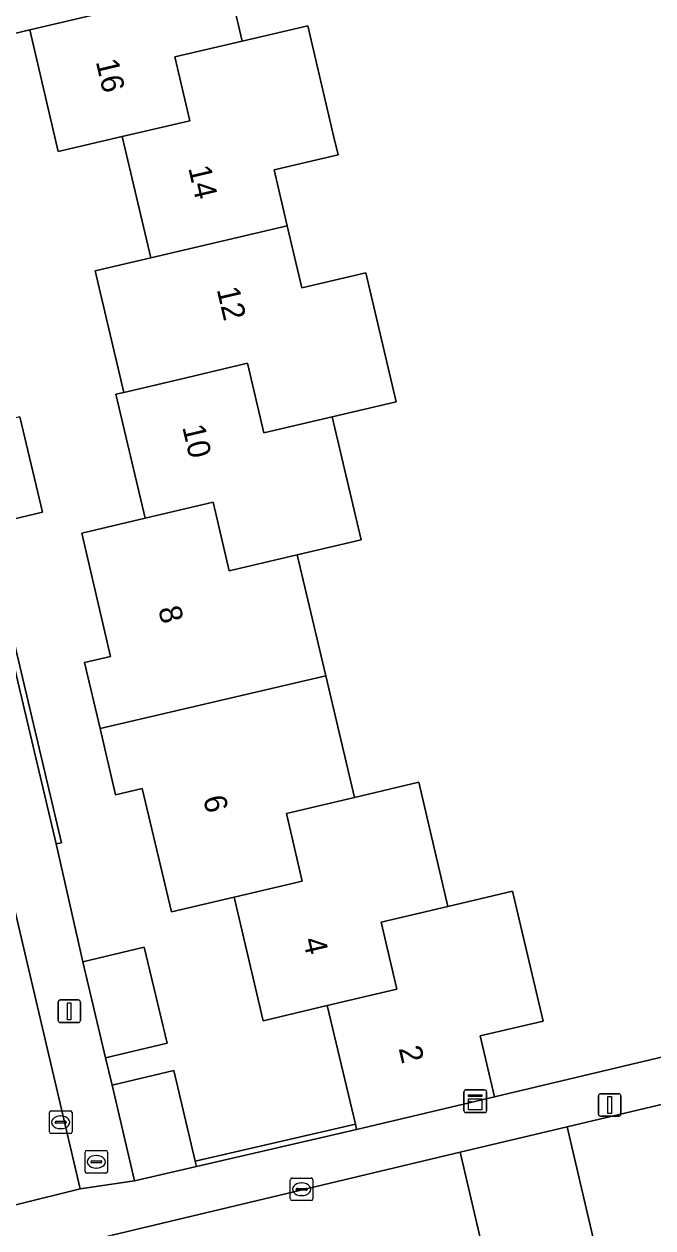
# Model space of a CAD drawing. Extents: x 158031 to 159244, y 380104 to 381214.
# Drawn here: x 158685 to 158712.9, y 380564.3 to 380617.5 of the extents above; entities that cross this region are included whole.
import ezdxf

# ---------------------------------------------------------------- set-up
doc = ezdxf.new("R2010")
doc.units = 0
for name, color, linetype in [('IMGEO_Brandkraan', 7, 'Continuous'), ('IMGEO_Erf', 7, 'Continuous'), ('IMGEO_Hek', 7, 'Continuous'), ('IMGEO_Kast', 7, 'Continuous'), ('IMGEO_Kolk', 7, 'Continuous'), ('IMGEO_Lichtmast', 7, 'Continuous'), ('IMGEO_Muur', 7, 'Continuous'), ('IMGEO_Pand', 7, 'Continuous'), ('IMGEO_Pand_nummerreeks', 7, 'Continuous'), ('IMGEO_Rijbaan_lokaal_open', 7, 'Continuous'), ('IMGEO_Voetpad_open', 7, 'Continuous')]:
    doc.layers.add(name, color=color, linetype=linetype)

msp = doc.modelspace()

# ---------------------------------------------------------------- linework, layer by layer
at = {"layer": 'IMGEO_Brandkraan'}
for p, q in [((158687.739, 380566.802), (158687.739, 380567.654)), ((158687.814, 380567.728), (158688.666, 380567.728)), ((158688.74, 380567.654), (158688.74, 380566.802)), ((158687.998, 380567.222), (158687.998, 380567.234)), ((158688.436, 380567.185), (158688.038, 380567.185)), ((158688.041, 380567.271), (158688.439, 380567.271)), ((158688.227, 380567.508), (158688.252, 380567.508)), ((158688.482, 380567.234), (158688.482, 380567.222)), ((158688.666, 380566.728), (158687.814, 380566.728)), ((158688.25, 380566.948), (158688.225, 380566.948))]:
    msp.add_line(p, q, dxfattribs=at)
for points in [[(158687.739, 380566.802), (158687.739, 380567.654)], [(158687.814, 380567.728), (158688.666, 380567.728)], [(158688.74, 380567.654), (158688.74, 380566.802)], [(158688.666, 380566.728), (158687.814, 380566.728)]]:
    msp.add_lwpolyline(points, dxfattribs=at)
for centre, radius, start, end in [((158687.816, 380567.652), 0.0765, 91.552, 178.448), ((158687.816, 380567.652), 0.0765, 91.552, 178.448), ((158688.664, 380567.652), 0.0765, 1.552, 88.448), ((158688.664, 380567.652), 0.0765, 1.552, 88.448), ((158688.038, 380567.231), 0.0403, 85.8775, 175.7526), ((158688.035, 380567.221), 0.0366, 178.938, 274.7102), ((158688.439, 380567.228), 0.043, 264.8664, 352.4533), ((158688.443, 380567.233), 0.0386, 1.7309, 96.639), ((158687.816, 380566.804), 0.0765, 181.552, 268.448), ((158687.816, 380566.804), 0.0765, 181.552, 268.448), ((158688.664, 380566.804), 0.0765, 271.552, 358.448), ((158688.664, 380566.804), 0.0765, 271.552, 358.448)]:
    msp.add_arc(centre, radius, start, end, dxfattribs=at)
for centre, major_axis, ratio, start_param, end_param in [((158688.226, 380567.228), (-0.387, 0.002), 0.722429, 4.712389, 7.853982), ((158688.251, 380567.228), (-0.39, 0.002), 0.717154, 1.570796, 4.712389)]:
    msp.add_ellipse(centre, major_axis=major_axis, ratio=ratio, start_param=start_param, end_param=end_param, dxfattribs=at)
at = {"layer": 'IMGEO_Erf'}
for points in [[(158693.404, 380622.278), (158694.695, 380616.786), (158697.593, 380617.467), (158698.737, 380612.6), (158698.935, 380611.759), (158696.103, 380611.093), (158696.687, 380608.61), (158697.331, 380605.871), (158700.164, 380606.537), (158701.504, 380600.839), (158698.669, 380600.173), (158699.948, 380594.732), (158697.13, 380594.07), (158698.388, 380588.719), (158699.652, 380583.342), (158702.502, 380584.012), (158703.792, 380578.525), (158706.65, 380579.197), (158708.002, 380573.446), (158705.217, 380572.792), (158705.856, 380570.103), (158725.953, 380574.878)], [(158684.603, 380590.209), (158686.699, 380581.338), (158686.465, 380581.283), (158687.636, 380576.078), (158690.36, 380576.726), (158691.369, 380572.481), (158688.645, 380571.833), (158688.935, 380570.621), (158691.661, 380571.259), (158692.614, 380567.25), (158699.697, 380568.888), (158698.452, 380574.133), (158695.623, 380573.469), (158694.339, 380578.933), (158691.557, 380578.279), (158690.274, 380583.739), (158689.093, 380583.461), (158688.406, 380586.385), (158687.719, 380589.309), (158688.872, 380589.58), (158687.591, 380595.031), (158690.393, 380595.689), (158689.105, 380601.169), (158689.457, 380601.252), (158688.194, 380606.62), (158690.646, 380607.197), (158689.384, 380612.566), (158686.557, 380611.902), (158685.293, 380617.279), (158682.451, 380616.611)], [(158684.859, 380600.175), (158685.852, 380595.949), (158683.126, 380595.308)]]:
    msp.add_lwpolyline(points, dxfattribs=at)
at = {"layer": 'IMGEO_Hek'}
msp.add_lwpolyline([(158705.856, 380570.103), (158725.953, 380574.878)], dxfattribs=at)
at = {"layer": 'IMGEO_Kast'}
for p, q in [((158704.499, 380569.479), (158704.499, 380570.32)), ((158704.499, 380570.32), (158704.499, 380569.479)), ((158704.574, 380570.404), (158705.415, 380570.404)), ((158705.415, 380570.404), (158704.574, 380570.404)), ((158705.499, 380570.329), (158705.499, 380569.488)), ((158705.499, 380569.488), (158705.499, 380570.329)), ((158705.424, 380569.404), (158704.583, 380569.404)), ((158704.583, 380569.404), (158705.424, 380569.404))]:
    msp.add_line(p, q, dxfattribs=at)
for points in [[(158704.694, 380570.194), (158705.294, 380570.194), (158705.294, 380570.109), (158704.694, 380570.109), (158704.694, 380570.194)], [(158704.694, 380570.019), (158705.294, 380570.019), (158705.294, 380569.53), (158704.694, 380569.53), (158704.694, 380570.019)]]:
    msp.add_lwpolyline(points, dxfattribs=at)
msp.add_circle((158704.778, 380569.868), 0.0377, dxfattribs=at)
for centre, start, end in [((158704.577, 380570.326), 92.4484, 184.2845), ((158704.577, 380570.326), 92.4484, 184.2845), ((158705.421, 380570.326), 2.4484, 94.2845), ((158705.421, 380570.326), 2.4484, 94.2845), ((158704.577, 380569.482), 182.4484, 274.2845), ((158704.577, 380569.482), 182.4484, 274.2845), ((158705.421, 380569.482), 272.4484, 4.2845), ((158705.421, 380569.482), 272.4484, 4.2845)]:
    msp.add_arc(centre, 0.0779, start, end, dxfattribs=at)
at = {"layer": 'IMGEO_Kolk'}
for p, q in [((158686.163, 380568.551), (158686.163, 380569.403)), ((158686.238, 380569.477), (158687.09, 380569.477)), ((158686.651, 380569.257), (158686.676, 380569.257)), ((158687.164, 380569.403), (158687.164, 380568.551)), ((158686.422, 380568.971), (158686.422, 380568.983)), ((158686.86, 380568.934), (158686.462, 380568.934)), ((158686.465, 380569.02), (158686.863, 380569.02)), ((158686.906, 380568.983), (158686.906, 380568.971)), ((158687.09, 380568.477), (158686.238, 380568.477)), ((158686.674, 380568.697), (158686.649, 380568.697)), ((158696.82, 380565.586), (158696.82, 380566.438)), ((158696.895, 380566.512), (158697.747, 380566.512)), ((158697.122, 380566.055), (158697.52, 380566.055)), ((158697.308, 380566.292), (158697.333, 380566.292)), ((158697.821, 380566.438), (158697.821, 380565.586)), ((158697.747, 380565.512), (158696.895, 380565.512)), ((158697.079, 380566.006), (158697.079, 380566.018)), ((158697.517, 380565.969), (158697.119, 380565.969)), ((158697.331, 380565.732), (158697.306, 380565.732)), ((158697.563, 380566.018), (158697.563, 380566.006))]:
    msp.add_line(p, q, dxfattribs=at)
for points in [[(158686.163, 380568.551), (158686.163, 380569.403)], [(158686.238, 380569.477), (158687.09, 380569.477)], [(158687.164, 380569.403), (158687.164, 380568.551)], [(158687.09, 380568.477), (158686.238, 380568.477)], [(158696.82, 380565.586), (158696.82, 380566.438)], [(158696.895, 380566.512), (158697.747, 380566.512)], [(158697.821, 380566.438), (158697.821, 380565.586)], [(158697.747, 380565.512), (158696.895, 380565.512)]]:
    msp.add_lwpolyline(points, dxfattribs=at)
for centre, radius, start, end in [((158686.24, 380569.401), 0.0765, 91.552, 178.448), ((158686.24, 380569.401), 0.0765, 91.552, 178.448), ((158687.088, 380569.401), 0.0765, 1.552, 88.448), ((158687.088, 380569.401), 0.0765, 1.552, 88.448), ((158686.462, 380568.98), 0.0403, 85.8775, 175.7526), ((158686.459, 380568.97), 0.0366, 178.938, 274.7102), ((158686.863, 380568.977), 0.043, 264.8664, 352.4533), ((158686.867, 380568.982), 0.0386, 1.7309, 96.639), ((158686.24, 380568.553), 0.0765, 181.552, 268.448), ((158686.24, 380568.553), 0.0765, 181.552, 268.448), ((158687.088, 380568.553), 0.0765, 271.552, 358.448), ((158687.088, 380568.553), 0.0765, 271.552, 358.448), ((158696.897, 380566.436), 0.0765, 91.552, 178.448), ((158696.897, 380566.436), 0.0765, 91.552, 178.448), ((158697.119, 380566.015), 0.0403, 85.8775, 175.7526), ((158697.524, 380566.017), 0.0386, 1.7309, 96.639), ((158697.745, 380566.436), 0.0765, 1.552, 88.448), ((158697.745, 380566.436), 0.0765, 1.552, 88.448), ((158696.897, 380565.588), 0.0765, 181.552, 268.448), ((158696.897, 380565.588), 0.0765, 181.552, 268.448), ((158697.116, 380566.005), 0.0366, 178.938, 274.7102), ((158697.52, 380566.012), 0.043, 264.8664, 352.4533), ((158697.745, 380565.588), 0.0765, 271.552, 358.448), ((158697.745, 380565.588), 0.0765, 271.552, 358.448)]:
    msp.add_arc(centre, radius, start, end, dxfattribs=at)
for centre, major_axis, ratio, start_param, end_param in [((158686.65, 380568.977), (-0.387, 0.002), 0.722429, 4.712389, 7.853982), ((158686.675, 380568.977), (-0.39, 0.002), 0.717154, 1.570796, 4.712389), ((158697.307, 380566.012), (-0.387, 0.002), 0.722429, 4.712389, 7.853982), ((158697.332, 380566.012), (-0.39, 0.002), 0.717154, 1.570796, 4.712389)]:
    msp.add_ellipse(centre, major_axis=major_axis, ratio=ratio, start_param=start_param, end_param=end_param, dxfattribs=at)
at = {"layer": 'IMGEO_Lichtmast'}
for p, q in [((158686.547, 380573.484), (158686.547, 380574.284)), ((158686.547, 380574.284), (158686.547, 380573.484)), ((158686.647, 380574.384), (158687.437, 380574.384)), ((158687.437, 380574.384), (158686.647, 380574.384)), ((158687.537, 380574.284), (158687.537, 380573.484)), ((158687.537, 380573.484), (158687.537, 380574.284)), ((158687.437, 380573.384), (158686.647, 380573.384)), ((158686.647, 380573.384), (158687.437, 380573.384)), ((158710.45, 380569.34), (158710.45, 380570.14)), ((158710.45, 380570.14), (158710.45, 380569.34)), ((158710.55, 380570.24), (158711.34, 380570.24)), ((158711.34, 380570.24), (158710.55, 380570.24)), ((158711.44, 380570.14), (158711.44, 380569.34)), ((158711.44, 380569.34), (158711.44, 380570.14)), ((158711.34, 380569.24), (158710.55, 380569.24)), ((158710.55, 380569.24), (158711.34, 380569.24))]:
    msp.add_line(p, q, dxfattribs=at)
for points in [[(158686.967, 380574.259), (158687.117, 380574.259), (158687.117, 380573.509), (158686.967, 380573.509), (158686.967, 380574.259)], [(158710.87, 380570.115), (158711.02, 380570.115), (158711.02, 380569.365), (158710.87, 380569.365), (158710.87, 380570.115)]]:
    msp.add_lwpolyline(points, dxfattribs=at)
for centre, start, end in [((158686.647, 380574.284), 90, 180), ((158686.647, 380574.284), 90, 180), ((158687.437, 380574.284), 0, 90), ((158687.437, 380574.284), 360, 90), ((158686.647, 380573.484), 180, 270), ((158686.647, 380573.484), 180, 270), ((158687.437, 380573.484), 270, 0), ((158687.437, 380573.484), 270, 0), ((158710.55, 380570.14), 90, 180), ((158710.55, 380570.14), 90, 180), ((158711.34, 380570.14), 0, 90), ((158711.34, 380570.14), 360, 90), ((158710.55, 380569.34), 180, 270), ((158710.55, 380569.34), 180, 270), ((158711.34, 380569.34), 270, 0), ((158711.34, 380569.34), 270, 0)]:
    msp.add_arc(centre, 0.1, start, end, dxfattribs=at)
at = {"layer": 'IMGEO_Muur'}
for points in [[(158686.699, 380581.338), (158684.603, 380590.209), (158684.369, 380590.154), (158686.465, 380581.283)], [(158692.614, 380567.25), (158692.67, 380567.017), (158699.753, 380568.654), (158699.697, 380568.888)]]:
    msp.add_lwpolyline(points, close=True, dxfattribs=at)
at = {"layer": 'IMGEO_Pand'}
for points in [[(158685.293, 380617.279), (158688.263, 380617.977), (158687.574, 380620.908), (158690.697, 380621.642), (158689.357, 380627.287), (158679.216, 380624.879), (158679.889, 380622.011), (158679.96, 380621.708), (158681.185, 380621.996), (158682.451, 380616.611)], [(158685.293, 380617.279), (158686.557, 380611.902), (158689.384, 380612.566), (158692.37, 380613.267), (158691.709, 380616.084), (158694.695, 380616.786), (158693.404, 380622.278), (158690.697, 380621.642), (158687.574, 380620.908), (158688.263, 380617.977)], [(158696.687, 380608.61), (158696.103, 380611.093), (158698.935, 380611.759), (158698.737, 380612.6), (158697.593, 380617.467), (158694.695, 380616.786), (158691.709, 380616.084), (158692.37, 380613.267), (158689.384, 380612.566), (158690.646, 380607.197)], [(158700.164, 380606.537), (158697.331, 380605.871), (158696.687, 380608.61), (158690.646, 380607.197), (158688.194, 380606.62), (158689.457, 380601.252), (158691.909, 380601.828), (158694.928, 380602.537), (158695.65, 380599.464), (158698.669, 380600.173), (158701.504, 380600.839)], [(158698.669, 380600.173), (158695.65, 380599.464), (158694.928, 380602.537), (158691.909, 380601.828), (158689.457, 380601.252), (158689.105, 380601.169), (158690.393, 380595.689), (158693.405, 380596.396), (158694.118, 380593.362), (158697.13, 380594.07), (158699.948, 380594.732)], [(158682.133, 380599.534), (158683.126, 380595.308), (158685.852, 380595.949), (158684.859, 380600.175)], [(158698.388, 380588.719), (158697.13, 380594.07), (158694.118, 380593.362), (158693.405, 380596.396), (158690.393, 380595.689), (158687.591, 380595.031), (158688.872, 380589.58), (158687.719, 380589.309), (158688.406, 380586.385)], [(158698.388, 380588.719), (158688.406, 380586.385), (158689.093, 380583.461), (158690.274, 380583.739), (158691.557, 380578.279), (158694.339, 380578.933), (158697.347, 380579.64), (158696.644, 380582.635), (158699.652, 380583.342)], [(158694.339, 380578.933), (158695.623, 380573.469), (158698.452, 380574.133), (158701.529, 380574.856), (158700.831, 380577.829), (158703.792, 380578.525), (158702.502, 380584.012), (158699.652, 380583.342), (158696.644, 380582.635), (158697.347, 380579.64)], [(158703.792, 380578.525), (158700.831, 380577.829), (158701.529, 380574.856), (158698.452, 380574.133), (158699.697, 380568.888), (158699.753, 380568.654), (158705.856, 380570.103), (158705.217, 380572.792), (158708.002, 380573.446), (158706.65, 380579.197)], [(158687.636, 380576.078), (158688.645, 380571.833), (158691.369, 380572.481), (158690.36, 380576.726)], [(158689.925, 380566.39), (158692.67, 380567.017), (158692.614, 380567.25), (158691.661, 380571.259), (158688.935, 380570.621)]]:
    msp.add_lwpolyline(points, close=True, dxfattribs=at)
at = {"layer": 'IMGEO_Rijbaan_lokaal_open'}
for points in [[(158674.8, 380595.318), (158681.44, 380567.252), (158682.048, 380564.681), (158687.531, 380566.04), (158675.144, 380618.798), (158674.853, 380618.727), (158646.289, 380611.903), (158642.774, 380611.091), (158641.644, 380615.902), (158637.085, 380614.819), (158638.238, 380610.014), (158643.37, 380588.22), (158643.438, 380587.928)], [(158704.337, 380567.651), (158705.699, 380561.785), (158710.43, 380562.906), (158709.071, 380568.78)], [(158704.337, 380567.651), (158688.944, 380563.986), (158681.626, 380562.216), (158678.162, 380561.39), (158679.597, 380555.533), (158705.699, 380561.785)]]:
    msp.add_lwpolyline(points, close=True, dxfattribs=at)
msp.add_lwpolyline([(158759.507, 380580.784), (158753.43, 380579.309), (158752.053, 380578.985), (158745.393, 380577.395), (158745.252, 380577.361), (158742.459, 380576.694), (158709.071, 380568.78), (158710.43, 380562.906), (158713.492, 380563.648), (158720.027, 380565.209), (158760.23, 380574.758)], dxfattribs=at)
at = {"layer": 'IMGEO_Voetpad_open'}
msp.add_lwpolyline([(158683.126, 380595.308), (158682.133, 380599.534), (158681.838, 380600.744), (158680.865, 380604.867), (158679.891, 380608.99), (158679.608, 380610.187), (158678.61, 380614.426), (158677.453, 380619.361), (158676.34, 380624.116), (158673.995, 380623.552), (158675.144, 380618.798), (158687.531, 380566.04), (158689.925, 380566.39), (158688.935, 380570.621), (158688.645, 380571.833), (158687.636, 380576.078), (158686.465, 380581.283), (158684.369, 380590.154)], close=True, dxfattribs=at)
msp.add_lwpolyline([(158688.944, 380563.986), (158704.337, 380567.651), (158709.071, 380568.78), (158742.459, 380576.694), (158742.026, 380578.534), (158739.029, 380577.884), (158736.103, 380577.249), (158725.953, 380574.878), (158705.856, 380570.103), (158699.753, 380568.654), (158692.67, 380567.017), (158689.925, 380566.39), (158687.531, 380566.04), (158682.048, 380564.681), (158681.44, 380567.252), (158678.049, 380566.443), (158664.016, 380563.096)], dxfattribs=at)

# ---------------------------------------------------------------- texts
at = {"layer": 'IMGEO_Pand_nummerreeks'}
for s, rotation, p in [('16', 283.2286, (158688.21, 380615.883)), ('14', 283.2274, (158692.3, 380611.174)), ('12', 283.2351, (158693.56, 380605.809)), ('10', 283.2294, (158692.035, 380599.719)), ('8', 283.3194, (158690.972, 380591.688)), ('6', 283.3194, (158692.954, 380583.315)), ('4', 283.2242, (158697.371, 380577.045)), ('2', 283.229, (158701.609, 380572.243))]:
    msp.add_text(s, height=1, rotation=rotation, dxfattribs=at).set_placement(p)

doc.saveas('drawing.dxf')
